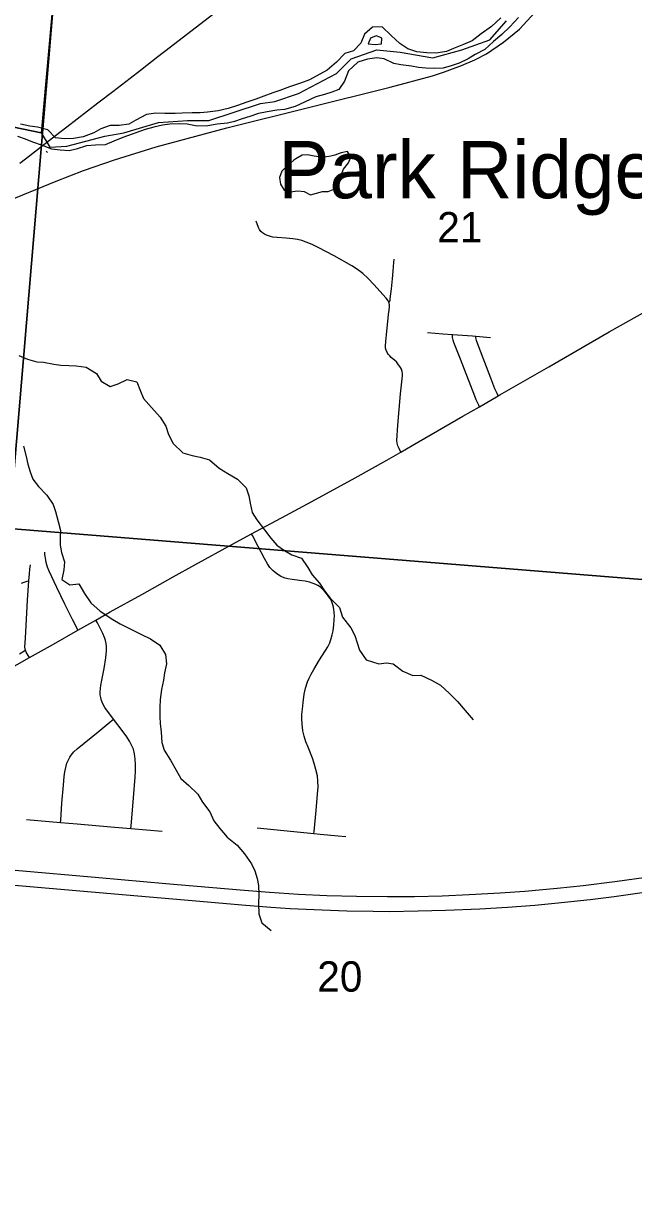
# Model space of a CAD drawing. Extents: x 0 to 1134, y 0 to 440.
# Drawn here: x 427.82 to 453.05, y 155.8 to 204.78 of the extents above; entities that cross this region are included whole.
import ezdxf

# ---------------------------------------------------------------- set-up
doc = ezdxf.new("R2010")
doc.units = 0
for name, color, linetype in [('GM_X_County_Road', 7, 'Continuous'), ('GM_X_Interstate_Route', 7, 'Continuous'), ('GM_X_Major_River', 7, 'Continuous'), ('GM_X_Minor_Lake', 7, 'Continuous'), ('GM_X_Minor_River', 7, 'Continuous'), ('GM_X_Rail_Line', 7, 'Continuous'), ('GM_X_Section', 7, 'Continuous'), ('GM_X_Section_Text', 7, 'Continuous'), ('GM_X_Township', 7, 'Continuous'), ('GM_X_Township_Road', 7, 'Continuous'), ('GM_X_Unincorporated', 7, 'Continuous'), ('GM_X_Unincorporated_Text', 7, 'Continuous')]:
    doc.layers.add(name, color=color, linetype=linetype)

msp = doc.modelspace()

# ---------------------------------------------------------------- linework, layer by layer
at = {"layer": 'GM_X_County_Road'}
msp.add_line((446.681, 188.933), (447.459, 189.381), dxfattribs=at)
for points in [[(447.459, 189.381), (447.527, 189.42), (449.545, 190.586), (452.052, 192.025), (455.057, 193.719), (458.551, 195.686), (459.017, 195.943)], [(443.423, 187.054), (443.894, 187.322), (445.992, 188.536), (446.681, 188.933)], [(437.25, 183.669), (438.673, 184.436), (439.74, 185.01), (441.54, 185.993), (442.841, 186.723), (443.423, 187.054)], [(430.81, 180.102), (431.404, 180.436), (432.705, 181.166), (434.006, 181.894), (434.903, 182.391), (436.458, 183.241), (437.25, 183.669)], [(430.061, 179.68), (430.185, 179.75), (430.81, 180.102)], [(428.056, 178.548), (429.048, 179.109), (430.061, 179.68)], [(417.044, 172.322), (417.874, 172.804), (419.366, 173.631), (420.352, 174.184), (421.619, 174.905), (423.143, 175.77), (428.056, 178.548)]]:
    msp.add_lwpolyline(points, dxfattribs=at)
at = {"layer": 'GM_X_Interstate_Route'}
for points in [[(427.47, 169.755), (430.926, 169.447), (433.705, 169.203), (436.776, 168.937), (437.996, 168.838), (439.195, 168.759), (440.357, 168.707), (441.598, 168.676), (442.87, 168.66), (443.996, 168.665), (445.133, 168.692), (446.248, 168.739), (447.531, 168.811), (448.563, 168.884), (449.898, 169.01), (450.967, 169.119), (452.275, 169.286), (455.982, 169.797), (456.546, 169.873)], [(427.437, 169.137), (432.061, 168.734), (434.481, 168.524), (436.847, 168.32), (438.048, 168.224), (438.853, 168.17), (440.168, 168.104), (441.189, 168.074), (442.276, 168.056), (442.949, 168.044), (444.137, 168.062), (445.278, 168.092), (446.696, 168.146), (447.837, 168.218), (448.966, 168.302), (449.801, 168.386), (451.26, 168.542), (452.251, 168.662), (453.608, 168.848), (454.605, 168.986), (455.716, 169.137), (456.239, 169.21)]]:
    msp.add_lwpolyline(points, dxfattribs=at)
at = {"layer": 'GM_X_Major_River'}
for points in [[(447.568, 205.019), (447.183, 204.662), (446.755, 204.363), (446.383, 204.075), (446.015, 203.923), (445.611, 203.75), (445.312, 203.631), (444.888, 203.56), (444.501, 203.58), (444.091, 203.623), (443.717, 203.745), (443.38, 203.958), (443.019, 204.288), (442.657, 204.652), (442.26, 204.639), (441.917, 204.344), (441.772, 203.982), (441.468, 203.658), (441.112, 203.551), (440.761, 203.194), (440.377, 202.86), (439.649, 202.465), (439.281, 202.325), (438.821, 202.175), (438.419, 202.024), (438.131, 201.928), (437.763, 201.788), (437.429, 201.658), (437.05, 201.529), (436.67, 201.401), (436.28, 201.272), (435.867, 201.179), (435.421, 201.12), (435.123, 201.092), (434.793, 201.1), (434.381, 201.086), (434.084, 201.069), (433.662, 201.067), (433.286, 201.075), (432.897, 201.027), (432.458, 200.797)], [(448.299, 205.037), (447.936, 204.657), (447.61, 204.333), (447.261, 204.044), (446.9, 203.721), (446.507, 203.513), (446.206, 203.326), (445.837, 203.151), (445.504, 203.044), (445.171, 202.949), (444.828, 202.934), (444.463, 202.942), (444.156, 202.971), (443.861, 203.023), (443.428, 203.078), (443.133, 203.131), (442.738, 203.333), (442.431, 203.374), (442.042, 203.314), (441.64, 203.186), (441.266, 202.829), (441.097, 202.399), (440.861, 202.062), (440.574, 201.954), (440.263, 201.847), (439.907, 201.752), (439.469, 201.545), (439.054, 201.36), (438.618, 201.233), (438.298, 201.205), (437.897, 201.134), (437.541, 201.062), (437.174, 200.945), (436.863, 200.849), (436.541, 200.73), (436.255, 200.668), (435.831, 200.62)], [(442.552, 204.221), (442.408, 204.278), (442.167, 204.19), (442.073, 203.952)], [(442.073, 203.952), (442.358, 203.925), (442.62, 203.945), (442.646, 204.184), (442.552, 204.221)], [(435.831, 200.62), (435.442, 200.56), (434.997, 200.547), (434.588, 200.625), (434.257, 200.632), (433.869, 200.618), (433.56, 200.579), (433.205, 200.507), (432.849, 200.4), (431.929, 200.078), (431.548, 199.915), (431.192, 199.775), (430.792, 199.749), (430.415, 199.724), (429.99, 199.596), (429.703, 199.522), (429.327, 199.542), (428.985, 199.595), (428.601, 199.74), (428.205, 199.875), (427.899, 200.007), (427.582, 200.116)], [(432.458, 200.797), (432.169, 200.621), (431.769, 200.572), (431.392, 200.569), (431.012, 200.429), (430.723, 200.264), (430.286, 200.103), (429.885, 200.032), (429.508, 200.017), (429.133, 200.06), (428.821, 200.386), (428.39, 200.498), (428.071, 200.539), (427.685, 200.628)]]:
    msp.add_lwpolyline(points, dxfattribs=at)
at = {"layer": 'GM_X_Minor_Lake'}
for points in [[(440.622, 197.915), (440.7, 197.942), (440.851, 198.202), (440.934, 198.463), (441.052, 198.758), (441.26, 199.029), (441.354, 199.256), (441.22, 199.496), (440.958, 199.443), (440.694, 199.343), (440.523, 199.3), (440.352, 199.267), (440.112, 199.259), (439.839, 199.296), (439.566, 199.356), (439.338, 199.336), (439.086, 199.191)], [(439.086, 199.191), (438.994, 199.135), (438.752, 198.91), (438.498, 198.674), (438.404, 198.413), (438.446, 198.139), (438.602, 197.887), (438.852, 197.827), (439.161, 197.869), (439.422, 197.832), (439.683, 197.703), (440.186, 197.834), (440.414, 197.843), (440.622, 197.915)]]:
    msp.add_lwpolyline(points, dxfattribs=at)
at = {"layer": 'GM_X_Minor_River'}
for points in [[(428.748, 199.514), (428.803, 199.45)], [(427.624, 191.056), (427.976, 190.904), (428.362, 190.786), (428.646, 190.771), (429.067, 190.686), (429.363, 190.649), (429.682, 190.633), (429.989, 190.618), (430.41, 190.568), (430.829, 190.301), (431.03, 189.991), (431.403, 189.77), (431.724, 189.88), (432.102, 190.058), (432.499, 189.962), (432.654, 189.573), (432.776, 189.276), (433.113, 188.896), (433.473, 188.505), (433.708, 188.126), (433.817, 187.783), (434.006, 187.405), (434.412, 187.024), (434.798, 186.906), (435.116, 186.845), (435.514, 186.738), (435.908, 186.392), (436.27, 186.171), (436.666, 185.939), (437.027, 185.581), (437.136, 185.25), (437.19, 184.941), (437.276, 184.553), (437.466, 184.255), (437.791, 183.841), (438.049, 183.485), (438.296, 183.197), (438.613, 182.977), (438.918, 182.803), (439.315, 182.661), (439.584, 182.271), (439.751, 181.973), (440.066, 181.627), (440.267, 181.306), (440.503, 181.007), (440.886, 180.627), (441.017, 180.215), (441.354, 179.779), (441.521, 179.469), (441.62, 179.16), (441.718, 178.863), (441.987, 178.461), (442.509, 178.296), (442.829, 178.326), (443.113, 178.289), (443.508, 177.988), (443.928, 177.812), (444.258, 177.82), (444.689, 177.61), (445.062, 177.412), (445.445, 177.065), (445.772, 176.731), (446.086, 176.363), (446.423, 175.972)], [(427.817, 187.295), (427.926, 186.872), (427.99, 186.553), (428.089, 186.233), (428.199, 185.935), (428.435, 185.636), (428.772, 185.268), (429.041, 184.889), (429.14, 184.592), (429.249, 184.18), (429.347, 183.815), (429.332, 183.519), (429.328, 183.2), (429.381, 182.903), (429.513, 182.514), (429.475, 182.184), (429.402, 181.775), (429.73, 181.566), (430.106, 181.596), (430.34, 181.195), (430.598, 180.816), (430.981, 180.47), (431.512, 180.122), (431.818, 179.947), (432.248, 179.726), (432.667, 179.516), (433.064, 179.329), (433.459, 179.062), (433.682, 178.672), (433.735, 178.296), (433.65, 177.921), (433.601, 177.614), (433.516, 177.228), (433.466, 176.819), (433.45, 176.477), (433.457, 176.101), (433.465, 175.816), (433.506, 175.463), (433.535, 175.041), (433.634, 174.721), (433.902, 174.308), (434.136, 173.895), (434.326, 173.551), (434.653, 173.262), (435.024, 172.893), (435.225, 172.572), (435.517, 172.17), (435.694, 171.792), (435.93, 171.482), (436.244, 171.114), (436.651, 170.79), (436.954, 170.422), (437.245, 170.009), (437.378, 169.722), (437.477, 169.402), (437.542, 169.117), (437.548, 168.741), (437.533, 168.376), (437.55, 167.944), (437.671, 167.578), (438.066, 167.254)]]:
    msp.add_lwpolyline(points, dxfattribs=at)
at = {"layer": 'GM_X_Rail_Line'}
for points in [[(427.659, 199.01), (428.072, 199.33), (428.589, 199.73), (429.14, 200.152), (429.609, 200.519), (430.891, 201.506), (431.505, 201.98), (432.224, 202.535), (432.648, 202.858), (433.378, 203.427), (433.9, 203.825), (434.559, 204.333), (440.221, 208.705)], [(426.942, 197.359), (429.163, 198.261), (430.295, 198.705), (431.573, 199.148), (433.297, 199.692), (436.23, 200.473), (442.989, 202.158), (444.734, 202.62), (445.237, 202.788), (445.937, 203.049), (446.49, 203.294), (446.975, 203.536), (447.679, 204.024), (448.33, 204.559), (449.291, 205.588)]]:
    msp.add_lwpolyline(points, dxfattribs=at)
at = {"layer": 'GM_X_Section'}
for points in [[(401.186, 216.549), (429.777, 214.186), (427.217, 183.893), (398.424, 186.464)], [(429.777, 214.186), (460.45, 211.914), (458.022, 181.403), (427.217, 183.893)], [(427.217, 183.893), (458.022, 181.403), (454.792, 151.155), (424.544, 153.681)]]:
    msp.add_lwpolyline(points, close=True, dxfattribs=at)
at = {"layer": 'GM_X_Township'}
for points in [[(429.276, 208.414), (428.546, 200.26), (426.606, 200.673)], [(426.606, 200.673), (428.546, 200.26), (428.906, 199.667), (429.601, 199.714), (431.176, 200.131), (431.963, 200.269), (433.399, 200.687), (434.603, 200.779), (435.483, 200.779), (437.614, 201.474), (438.216, 201.567), (439.189, 201.891), (440.763, 202.725), (441.365, 203.327), (442.43, 203.698), (443.403, 203.605), (444.746, 203.373), (445.95, 203.698), (447.108, 204.115), (447.803, 204.902)]]:
    msp.add_lwpolyline(points, dxfattribs=at)
at = {"layer": 'GM_X_Township_Road'}
for p, q in [((446.527, 191.851), (447.142, 191.797)), ((427.94, 171.851), (429.344, 171.729)), ((432.257, 171.478), (433.552, 171.372)), ((437.475, 171.51), (439.83, 171.271))]:
    msp.add_line(p, q, dxfattribs=at)
for points in [[(442.923, 193.254), (442.897, 193.313), (442.876, 193.348), (442.818, 193.42), (442.311, 193.986), (442.056, 194.256), (441.852, 194.446), (441.632, 194.616), (441.398, 194.767), (440.667, 195.17), (440.009, 195.516), (439.759, 195.639), (439.502, 195.746), (439.326, 195.805), (439.146, 195.849), (438.962, 195.879), (438.685, 195.904), (438.314, 195.928), (438.13, 195.952), (438.039, 195.971), (437.95, 195.998), (437.863, 196.032), (437.78, 196.072), (437.703, 196.125), (437.637, 196.189), (437.582, 196.264), (437.54, 196.347), (437.446, 196.608)], [(442.923, 193.254), (442.94, 193.267), (442.965, 193.297), (442.979, 193.344), (442.991, 193.399), (443.042, 193.809), (443.077, 194.226), (443.106, 194.547), (443.122, 194.734), (443.136, 194.904), (443.15, 195.038)], [(443.423, 187.054), (443.413, 187.075), (443.354, 187.199), (443.307, 187.307), (443.277, 187.419), (443.266, 187.537), (443.308, 188.174), (443.414, 189.468), (443.493, 190.207), (443.495, 190.3), (443.482, 190.392), (443.451, 190.479), (443.405, 190.559), (443.3, 190.712), (443.24, 190.784), (443.173, 190.848), (443.03, 190.966), (442.964, 191.031), (442.906, 191.104), (442.857, 191.182), (442.818, 191.267), (442.793, 191.356), (442.786, 191.448), (442.8, 191.634), (442.836, 191.91), (442.918, 192.741), (442.939, 192.926), (442.95, 193.08), (442.952, 193.142), (442.949, 193.183), (442.94, 193.218), (442.923, 193.254)], [(444.528, 192.005), (445.163, 191.951), (445.557, 191.923)], [(446.681, 188.933), (446.647, 189.002), (446.544, 189.216), (446.49, 189.373), (445.89, 190.901), (445.615, 191.593), (445.585, 191.681), (445.564, 191.793), (445.558, 191.892), (445.557, 191.923)], [(445.557, 191.923), (446.389, 191.864), (446.527, 191.851)], [(447.459, 189.381), (447.41, 189.483), (447.32, 189.671), (447.146, 190.119), (446.658, 191.408), (446.559, 191.667), (446.546, 191.726), (446.533, 191.812), (446.527, 191.851)], [(439.83, 171.271), (439.838, 171.35), (439.919, 172.227), (439.984, 172.892), (440.005, 173.198), (439.992, 173.43), (439.972, 173.65), (439.915, 173.916), (439.842, 174.168), (439.768, 174.385), (439.585, 174.845), (439.499, 175.062), (439.421, 175.294), (439.373, 175.514), (439.352, 175.673), (439.344, 175.792), (439.332, 176.028), (439.332, 176.187), (439.352, 176.42), (439.381, 176.693), (439.43, 177.04), (439.487, 177.288), (439.568, 177.545), (439.638, 177.7), (439.711, 177.864), (439.821, 178.059), (440.062, 178.451), (440.4, 178.997), (440.486, 179.164), (440.515, 179.25), (440.547, 179.34), (440.588, 179.495), (440.625, 179.662), (440.653, 179.903), (440.669, 180.123), (440.678, 180.27), (440.669, 180.433), (440.657, 180.539), (440.637, 180.629), (440.612, 180.731), (440.584, 180.812), (440.551, 180.898), (440.502, 180.992), (440.453, 181.069), (440.396, 181.151), (440.343, 181.216), (440.274, 181.293), (440.205, 181.371), (440.103, 181.457), (439.988, 181.526), (439.907, 181.575), (439.801, 181.62), (439.65, 181.669), (439.47, 181.705), (439.226, 181.742), (438.932, 181.775), (438.748, 181.807), (438.642, 181.836), (438.536, 181.877), (438.447, 181.918), (438.337, 181.983), (438.227, 182.064), (438.129, 182.154), (438.01, 182.281), (437.908, 182.432), (437.778, 182.652), (437.521, 183.141), (437.284, 183.602), (437.25, 183.669)], [(430.061, 179.68), (430.013, 179.778), (429.84, 180.129), (429.529, 180.761), (429.188, 181.454), (428.877, 182.127), (428.811, 182.289), (428.757, 182.485), (428.738, 182.58), (428.721, 182.668), (428.708, 182.747), (428.699, 182.815), (428.692, 182.873), (428.689, 182.91)], [(428.028, 181.727), (428.06, 182.02), (428.081, 182.202), (428.098, 182.383)], [(427.729, 181.625), (427.84, 181.669), (427.97, 181.713), (428.028, 181.727)], [(427.892, 178.851), (427.882, 178.9), (427.874, 178.991), (427.889, 179.355), (427.984, 180.919), (428.028, 181.727)], [(431.541, 176), (431.175, 176.477), (431.098, 176.635), (431.042, 176.772), (431.007, 176.894), (430.991, 177.012), (430.991, 177.124), (431.001, 177.277), (431.012, 177.394), (431.053, 177.618), (431.144, 178.102), (431.22, 178.54), (431.251, 178.83), (431.251, 179.014), (431.231, 179.136), (431.205, 179.253), (431.159, 179.386), (431.093, 179.549), (430.869, 179.987), (430.81, 180.102)], [(427.892, 178.851), (427.822, 178.807), (427.642, 178.696)], [(428.056, 178.548), (428.002, 178.64), (427.927, 178.767), (427.906, 178.812), (427.892, 178.851)], [(429.344, 171.729), (429.351, 171.825), (429.401, 172.526), (429.47, 173.265), (429.501, 173.634), (429.524, 173.818), (429.559, 174), (429.608, 174.179), (429.642, 174.265), (429.682, 174.349), (429.728, 174.429), (429.779, 174.506), (429.896, 174.651), (430.029, 174.779), (430.897, 175.476), (431.4, 175.886), (431.541, 176)], [(432.257, 171.478), (432.265, 171.566), (432.367, 172.747), (432.438, 173.603), (432.443, 173.843), (432.453, 174.128), (432.438, 174.342), (432.408, 174.561), (432.362, 174.755), (432.301, 174.903), (432.204, 175.096), (432.087, 175.274), (431.939, 175.483), (431.541, 176)], [(429.344, 171.729), (430.03, 171.669), (431.42, 171.546), (432.257, 171.478)], [(439.83, 171.271), (440.09, 171.245), (440.838, 171.171), (441.143, 171.146)]]:
    msp.add_lwpolyline(points, dxfattribs=at)
at = {"layer": 'GM_X_Unincorporated'}
msp.add_lwpolyline([(429.276, 208.414), (428.546, 200.26), (428.906, 199.667), (429.601, 199.714), (431.176, 200.131), (431.963, 200.269), (433.399, 200.687), (434.603, 200.779), (435.483, 200.779), (437.614, 201.474), (438.216, 201.567), (439.189, 201.891), (440.763, 202.725), (441.365, 203.327), (442.43, 203.698), (443.403, 203.605), (444.746, 203.373), (445.95, 203.698), (447.108, 204.115), (447.803, 204.902)], dxfattribs=at)

# ---------------------------------------------------------------- texts
at = {"layer": 'GM_X_Section_Text'}
for s, p in [('21', (444.932, 195.733)), ('20', (439.969, 164.724))]:
    msp.add_text(s, height=1.2557, rotation=0, dxfattribs=at).set_placement(p)
at = {"layer": 'GM_X_Unincorporated_Text'}
msp.add_text('Park Ridge Acres', height=2.36932, rotation=0, dxfattribs=at).set_placement((438.357, 197.558))

doc.saveas('drawing.dxf')
